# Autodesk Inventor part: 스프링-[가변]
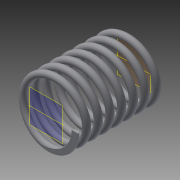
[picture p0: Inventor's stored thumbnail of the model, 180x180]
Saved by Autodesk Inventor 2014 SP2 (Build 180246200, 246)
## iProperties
Created: 2015-01
Part Number: 스프링-[가변]
Material: 강철, 탄소
Document SubType Name: Modeling
Designer: 201-09
Density: 7.87 g/cm^3
Appearance: 반연마
Author: 201-09
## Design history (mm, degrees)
node "작업 평면1"
node "작업축1"
  node "작업 평면2"
node "작업축2"
sketch "스케치1"
  geometry: L1 (-3.9, 8.693)-(23.4, 8.693) reference; L2 (0, -50.176)-(0, 8.363) reference; C1 r 2 at (17.5, -39.807); 3 further points; 1 other entity
  constraints: 1 centre point, 2 other
  dimensions: "d2" = 4 diameter of C1; "d3" = 17.5 distance from line of C1.centre L2; "d4" = 48.5 dimension on L1 (derived)
feature "코일1" sketch "스케치1" pitch "d5" = 10; turns "d7" = 7.5; dims "d6" = 48.5 (= d4), "d8" = 0, angle "d9" = 90 deg, angle "d10" = 90 deg, "d11" = 0, "d12" = 0
feature "분할1"
feature "분할2"
node "솔리드1"
other parameters: "d0" = 0, "d1" = 53.5
